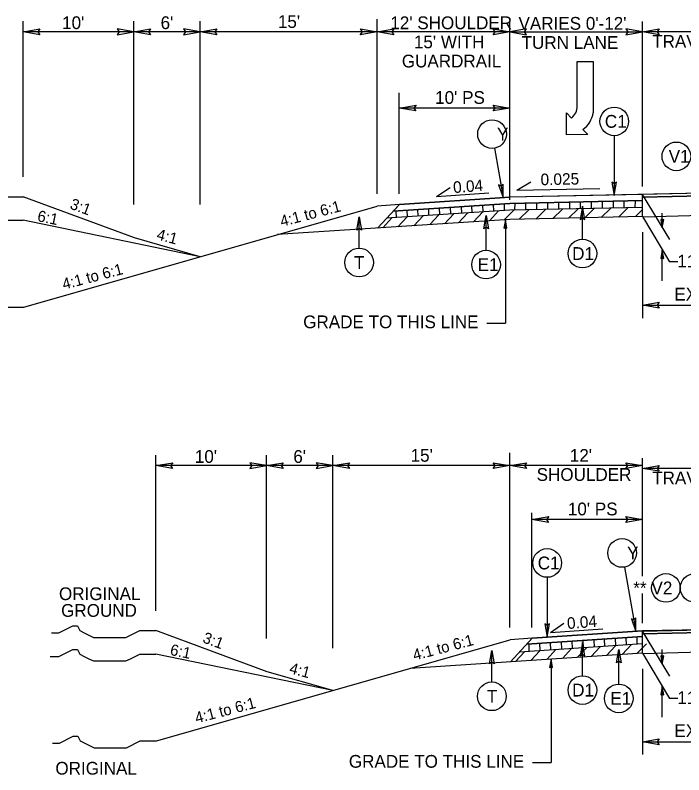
# Model space of a CAD drawing. Extents: x 2176024 to 2177225, y 75947 to 76635.
# Drawn here: x 2176665.1 to 2176725.6, y 76500.8 to 76569.5 of the extents above; entities that cross this region are included whole.
import ezdxf

# ---------------------------------------------------------------- set-up
doc = ezdxf.new("R2010")
doc.units = 0
for name, color, linetype in [('Exist XS Ground Line', 7, 'Continuous'), ('Old_Level_1', 7, 'Continuous'), ('Old_Level_11', 7, 'Continuous'), ('Prop Dimension', 7, 'Continuous'), ('Prop Lane Arrow CELL', 7, 'Continuous'), ('Typical Curb CELL', 7, 'Continuous'), ('Typical Pavement Slope CELL', 7, 'Continuous'), ('Typical Pavement Slope Information CELL', 7, 'Continuous'), ('Typical Shoulder Slope CELL', 7, 'Continuous'), ('Typical Slope Point Local CELL', 7, 'Continuous'), ('Typical Terminator CELL', 7, 'Continuous'), ('Typical Text General CELL', 7, 'Continuous')]:
    doc.layers.add(name, color=color, linetype=linetype)

msp = doc.modelspace()

# ---------------------------------------------------------------- linework, layer by layer
at = {"layer": 'Exist XS Ground Line'}
for p, q in [((2176733.841, 76551.535), (2176721.841, 76551.184)), ((2176733.841, 76512.056), (2176721.841, 76511.705))]:
    msp.add_line(p, q, dxfattribs=at)
at = {"layer": 'Old_Level_1'}
for p, q in [((2176705.492, 76551.53), (2176705.469, 76552.149)), ((2176706.442, 76551.591), (2176706.419, 76552.212)), ((2176707.429, 76551.663), (2176707.406, 76552.276)), ((2176708.384, 76551.72), (2176708.361, 76552.339)), ((2176709.371, 76551.788), (2176709.349, 76552.404)), ((2176710.306, 76551.827), (2176710.312, 76552.446)), ((2176711.294, 76551.855), (2176711.299, 76552.466)), ((2176712.283, 76551.869), (2176712.288, 76552.487)), ((2176713.28, 76551.892), (2176713.285, 76552.508)), ((2176714.269, 76551.911), (2176714.275, 76552.528)), ((2176715.259, 76551.936), (2176715.264, 76552.549)), ((2176716.24, 76551.956), (2176716.245, 76552.57)), ((2176717.219, 76551.977), (2176717.224, 76552.59)), ((2176718.216, 76551.984), (2176718.221, 76552.611)), ((2176719.205, 76552.013), (2176719.21, 76552.631)), ((2176720.179, 76552.025), (2176720.184, 76552.652)), ((2176721.185, 76552.05), (2176721.191, 76552.673)), ((2176699.602, 76551.142), (2176699.58, 76551.763)), ((2176700.589, 76551.215), (2176700.567, 76551.828)), ((2176701.545, 76551.271), (2176701.522, 76551.89)), ((2176702.532, 76551.339), (2176702.509, 76551.955)), ((2176703.519, 76551.4), (2176703.497, 76552.02)), ((2176703.939, 76550.593), (2176704.767, 76551.483)), ((2176704.504, 76551.473), (2176704.482, 76552.084)), ((2176705.196, 76550.681), (2176706.003, 76551.564)), ((2176706.57, 76550.766), (2176707.388, 76551.66)), ((2176708.014, 76550.864), (2176708.833, 76551.76)), ((2176709.34, 76550.954), (2176710.214, 76551.828)), ((2176710.69, 76551.002), (2176711.556, 76551.854)), ((2176712.188, 76551.018), (2176713.071, 76551.885)), ((2176713.725, 76551.068), (2176714.591, 76551.92)), ((2176715.155, 76551.105), (2176716.012, 76551.948)), ((2176716.613, 76551.132), (2176717.477, 76551.982)), ((2176718.111, 76551.147), (2176718.98, 76552.002)), ((2176719.66, 76551.186), (2176720.526, 76552.038)), ((2176721.17, 76551.223), (2176721.838, 76551.881)), ((2176698.357, 76550.232), (2176699.164, 76551.115)), ((2176699.73, 76550.317), (2176700.548, 76551.211)), ((2176701.175, 76550.415), (2176701.994, 76551.311)), ((2176702.617, 76550.512), (2176703.427, 76551.397)), ((2176717.492, 76512.301), (2176717.467, 76512.981)), ((2176718.442, 76512.362), (2176718.417, 76513.044)), ((2176719.429, 76512.435), (2176719.404, 76513.108)), ((2176720.384, 76512.492), (2176720.359, 76513.171)), ((2176721.371, 76512.56), (2176721.346, 76513.236)), ((2176711.602, 76511.913), (2176711.578, 76512.595)), ((2176712.589, 76511.986), (2176712.565, 76512.66)), ((2176713.545, 76512.043), (2176713.52, 76512.722)), ((2176714.532, 76512.111), (2176714.507, 76512.787)), ((2176715.519, 76512.171), (2176715.494, 76512.852)), ((2176716.504, 76512.244), (2176716.48, 76512.916)), ((2176717.196, 76511.452), (2176718.003, 76512.335)), ((2176718.57, 76511.537), (2176719.388, 76512.432)), ((2176720.014, 76511.636), (2176720.833, 76512.531)), ((2176721.34, 76511.725), (2176722.214, 76512.599)), ((2176710.357, 76511.003), (2176711.164, 76511.886)), ((2176711.73, 76511.088), (2176712.548, 76511.983)), ((2176713.175, 76511.187), (2176713.994, 76512.083)), ((2176714.617, 76511.283), (2176715.427, 76512.168)), ((2176715.939, 76511.364), (2176716.767, 76512.254))]:
    msp.add_line(p, q, dxfattribs=at)
at = {"layer": 'Old_Level_11'}
for p, q in [((2176719.287, 76558.556), (2176719.287, 76553.141)), ((2176708.457, 76557.423), (2176709.243, 76552.962)), ((2176716.409, 76549.196), (2176716.409, 76552.192)), ((2176696.216, 76548.384), (2176696.216, 76551.226)), ((2176707.695, 76548.197), (2176707.695, 76551.33)), ((2176720.218, 76519.542), (2176721.243, 76513.723)), ((2176713.218, 76518.621), (2176713.218, 76513.207)), ((2176716.409, 76509.717), (2176716.409, 76512.714)), ((2176708.216, 76509.155), (2176708.216, 76511.997)), ((2176719.695, 76508.968), (2176719.695, 76512.101))]:
    msp.add_line(p, q, dxfattribs=at)
for points in [[(2176708.831, 76554.108), (2176709.243, 76552.962), (2176709.243, 76554.187), (2176709.06, 76553.999)], [(2176719.08, 76554.341), (2176719.287, 76553.141), (2176719.5, 76554.348), (2176719.287, 76554.195)], [(2176716.616, 76550.992), (2176716.409, 76552.192), (2176716.196, 76550.986), (2176716.409, 76551.139)], [(2176696.01, 76550.026), (2176696.216, 76551.226), (2176696.43, 76550.019), (2176696.216, 76550.173)], [(2176707.488, 76550.13), (2176707.695, 76551.33), (2176707.908, 76550.123), (2176707.695, 76550.276)], [(2176713.012, 76514.407), (2176713.218, 76513.207), (2176713.432, 76514.413), (2176713.218, 76514.26)], [(2176720.831, 76514.869), (2176721.243, 76513.723), (2176721.243, 76514.948), (2176721.06, 76514.76)], [(2176716.616, 76511.514), (2176716.409, 76512.714), (2176716.196, 76511.507), (2176716.409, 76511.66)], [(2176708.01, 76510.797), (2176708.216, 76511.997), (2176708.43, 76510.791), (2176708.216, 76510.944)], [(2176719.488, 76510.901), (2176719.695, 76512.101), (2176719.908, 76510.894), (2176719.695, 76511.048)]]:
    msp.add_lwpolyline(points, close=True, dxfattribs=at)
for centre in [(2176719.287, 76559.852), (2176708.233, 76558.699), (2176724.9, 76556.689), (2176716.409, 76547.9), (2176696.216, 76547.088), (2176707.695, 76546.901), (2176719.994, 76520.819), (2176713.218, 76519.917), (2176723.958, 76517.659), (2176726.55, 76517.659), (2176716.409, 76508.421), (2176708.216, 76507.859), (2176719.695, 76507.672)]:
    msp.add_circle(centre, 1.296, dxfattribs=at)
at = {"layer": 'Prop Dimension'}
for p, q in [((2176665.841, 76554.828), (2176665.841, 76568.9)), ((2176675.841, 76552.323), (2176675.841, 76568.9)), ((2176681.841, 76552.323), (2176681.841, 76568.9)), ((2176697.841, 76553.312), (2176697.841, 76569.11)), ((2176709.841, 76552.751), (2176709.841, 76568.874)), ((2176721.841, 76553.949), (2176721.841, 76568.874)), ((2176675.841, 76567.947), (2176665.841, 76567.947)), ((2176681.841, 76567.947), (2176675.841, 76567.947)), ((2176697.841, 76567.947), (2176681.841, 76567.947)), ((2176709.841, 76567.947), (2176697.841, 76567.947)), ((2176709.841, 76567.947), (2176721.841, 76567.947)), ((2176733.841, 76567.947), (2176721.947, 76567.947)), ((2176699.841, 76553.312), (2176699.841, 76562.434)), ((2176709.841, 76561.059), (2176699.841, 76561.059)), ((2176721.796, 76553.238), (2176724.266, 76549.156)), ((2176723.629, 76550.231), (2176723.629, 76551.559)), ((2176709.441, 76550.96), (2176709.441, 76541.605)), ((2176721.841, 76551.237), (2176724.266, 76547.142)), ((2176721.841, 76549.82), (2176721.841, 76542.068)), ((2176723.629, 76545.441), (2176723.629, 76548.217)), ((2176725.046, 76547.142), (2176724.266, 76547.142)), ((2176721.841, 76543.223), (2176745.841, 76543.223)), ((2176707.768, 76541.605), (2176709.441, 76541.605)), ((2176677.841, 76515.6), (2176677.841, 76529.672)), ((2176687.841, 76513.095), (2176687.841, 76529.672)), ((2176693.841, 76512.22), (2176693.841, 76529.672)), ((2176709.841, 76514.083), (2176709.841, 76529.881)), ((2176721.841, 76518.725), (2176721.841, 76529.396)), ((2176687.841, 76528.718), (2176677.841, 76528.718)), ((2176693.841, 76528.718), (2176687.841, 76528.718)), ((2176709.841, 76528.718), (2176693.841, 76528.718)), ((2176721.841, 76528.718), (2176709.841, 76528.718)), ((2176733.841, 76528.468), (2176721.947, 76528.468)), ((2176711.841, 76514.083), (2176711.841, 76524.463)), ((2176721.841, 76523.846), (2176711.841, 76523.846)), ((2176721.841, 76514.47), (2176721.841, 76517.15)), ((2176721.796, 76513.759), (2176724.266, 76509.677)), ((2176721.841, 76511.758), (2176724.266, 76507.663)), ((2176723.629, 76510.752), (2176723.629, 76512.08)), ((2176713.568, 76511.215), (2176713.568, 76501.859)), ((2176721.841, 76510.341), (2176721.841, 76502.59)), ((2176723.629, 76505.963), (2176723.629, 76508.739)), ((2176725.046, 76507.663), (2176724.266, 76507.663)), ((2176721.841, 76503.745), (2176745.841, 76503.745)), ((2176711.895, 76501.859), (2176713.568, 76501.859))]:
    msp.add_line(p, q, dxfattribs=at)
at = {"layer": 'Prop Lane Arrow CELL'}
for p, q in [((2176715.926, 76561.247), (2176715.934, 76565.262)), ((2176715.934, 76565.262), (2176717.382, 76565.26)), ((2176717.382, 76565.26), (2176717.373, 76560.63)), ((2176714.978, 76558.638), (2176714.96, 76560.613)), ((2176714.96, 76560.613), (2176715.42, 76560.151)), ((2176716.449, 76559.118), (2176716.909, 76558.657)), ((2176716.909, 76558.657), (2176714.978, 76558.638))]:
    msp.add_line(p, q, dxfattribs=at)
for centre, radius, start, end in [((2176714.497, 76561.245), 1.437, 310.23549, 359.89367), ((2176715.103, 76560.982), 2.305, 305.9059, 351.2176)]:
    msp.add_arc(centre, radius, start, end, dxfattribs=at)
at = {"layer": 'Typical Curb CELL'}
for p, q in [((2176721.841, 76551.237), (2176721.841, 76553.251)), ((2176721.841, 76511.758), (2176721.841, 76513.772))]:
    msp.add_line(p, q, dxfattribs=at)
at = {"layer": 'Typical Pavement Slope CELL'}
for p, q in [((2176745.841, 76553.751), (2176709.841, 76553.001)), ((2176745.17, 76553.487), (2176721.841, 76553.001)), ((2176699.86, 76552.346), (2176709.841, 76553.001)), ((2176699.86, 76552.346), (2176697.889, 76550.202)), ((2176709.841, 76552.436), (2176699.307, 76551.745)), ((2176721.841, 76552.686), (2176709.841, 76552.436)), ((2176709.841, 76551.819), (2176698.703, 76551.088)), ((2176721.841, 76552.069), (2176709.841, 76551.819)), ((2176681.841, 76547.612), (2176665.841, 76550.907)), ((2176709.841, 76550.987), (2176688.831, 76549.608)), ((2176711.86, 76513.117), (2176721.841, 76513.772)), ((2176745.841, 76514.272), (2176721.841, 76513.772)), ((2176745.17, 76514.008), (2176721.841, 76513.522)), ((2176711.86, 76513.117), (2176709.889, 76510.974)), ((2176721.841, 76513.268), (2176711.367, 76512.581)), ((2176721.841, 76512.59), (2176710.703, 76511.86)), ((2176693.841, 76508.383), (2176677.841, 76511.678)), ((2176721.841, 76511.758), (2176700.831, 76510.379))]:
    msp.add_line(p, q, dxfattribs=at)
at = {"layer": 'Typical Pavement Slope Information CELL'}
for p, q in [((2176710.482, 76553.633), (2176711.743, 76554.395)), ((2176703.213, 76553.061), (2176704.436, 76553.883)), ((2176710.482, 76553.633), (2176717.987, 76553.783)), ((2176703.213, 76553.061), (2176707.959, 76553.387)), ((2176713.508, 76513.637), (2176714.731, 76514.46)), ((2176713.508, 76513.637), (2176718.254, 76513.964))]:
    msp.add_line(p, q, dxfattribs=at)
at = {"layer": 'Typical Shoulder Slope CELL'}
for p, q in [((2176675.894, 76549.31), (2176665.841, 76553.036)), ((2176665.887, 76543.056), (2176697.86, 76552.186)), ((2176699.86, 76552.346), (2176697.86, 76552.186)), ((2176721.841, 76551.237), (2176709.841, 76550.987)), ((2176681.841, 76547.612), (2176675.894, 76549.31)), ((2176687.894, 76510.081), (2176677.841, 76513.807)), ((2176733.841, 76514.022), (2176721.841, 76513.72)), ((2176677.887, 76503.828), (2176709.86, 76512.957)), ((2176711.86, 76513.117), (2176709.86, 76512.957)), ((2176693.841, 76508.383), (2176687.894, 76510.081))]:
    msp.add_line(p, q, dxfattribs=at)
at = {"layer": 'Typical Slope Point Local CELL'}
for p, q in [((2176733.841, 76553.501), (2176721.841, 76553.251)), ((2176721.841, 76553.001), (2176745.17, 76553.487)), ((2176709.841, 76553.001), (2176699.86, 76552.346)), ((2176721.841, 76553.251), (2176709.841, 76553.001)), ((2176721.841, 76552.686), (2176721.841, 76553.251)), ((2176721.841, 76553.251), (2176721.841, 76553.001)), ((2176699.307, 76551.745), (2176709.841, 76552.436)), ((2176699.86, 76552.346), (2176699.307, 76551.745)), ((2176709.841, 76552.436), (2176721.841, 76552.686)), ((2176721.841, 76513.772), (2176711.86, 76513.117)), ((2176733.841, 76514.022), (2176721.841, 76513.772)), ((2176721.841, 76513.522), (2176745.17, 76514.008)), ((2176721.841, 76513.268), (2176721.841, 76513.772)), ((2176721.841, 76513.772), (2176721.841, 76513.522)), ((2176711.367, 76512.581), (2176721.841, 76513.268)), ((2176711.86, 76513.117), (2176711.367, 76512.581))]:
    msp.add_line(p, q, dxfattribs=at)
for points in [[(2176656.406, 76552.828), (2176656.651, 76552.828), (2176657.068, 76552.828), (2176657.486, 76553.036), (2176657.904, 76553.245), (2176658.321, 76553.455), (2176658.739, 76553.455), (2176658.949, 76553.036), (2176659.366, 76552.828), (2176659.784, 76552.618), (2176660.202, 76552.41), (2176660.619, 76552.41), (2176661.037, 76552.41), (2176661.455, 76552.41), (2176661.872, 76552.41), (2176662.29, 76552.41), (2176662.708, 76552.41), (2176663.125, 76552.41), (2176663.543, 76552.618), (2176663.96, 76552.828), (2176664.378, 76553.036), (2176665.005, 76553.036), (2176665.423, 76553.036), (2176665.841, 76553.036)], [(2176656.273, 76550.699), (2176656.651, 76550.699), (2176657.068, 76550.699), (2176657.486, 76550.907), (2176657.904, 76551.116), (2176658.321, 76551.326), (2176658.739, 76551.326), (2176658.949, 76550.907), (2176659.366, 76550.699), (2176659.784, 76550.489), (2176660.202, 76550.281), (2176660.619, 76550.281), (2176661.037, 76550.281), (2176661.455, 76550.281), (2176661.872, 76550.281), (2176662.29, 76550.281), (2176662.708, 76550.281), (2176663.125, 76550.281), (2176663.543, 76550.489), (2176663.96, 76550.699), (2176664.378, 76550.907), (2176665.005, 76550.907), (2176665.423, 76550.907), (2176665.841, 76550.907)], [(2176656.497, 76542.848), (2176656.697, 76542.848), (2176657.115, 76542.848), (2176657.533, 76543.056), (2176657.95, 76543.266), (2176658.368, 76543.476), (2176658.786, 76543.476), (2176658.995, 76543.056), (2176659.413, 76542.848), (2176659.831, 76542.639), (2176660.248, 76542.431), (2176660.666, 76542.431), (2176661.084, 76542.431), (2176661.501, 76542.431), (2176661.919, 76542.431), (2176662.337, 76542.431), (2176662.754, 76542.431), (2176663.172, 76542.431), (2176663.589, 76542.639), (2176664.007, 76542.848), (2176664.425, 76543.056), (2176665.052, 76543.056), (2176665.47, 76543.056), (2176665.887, 76543.056)], [(2176668.406, 76513.599), (2176668.651, 76513.599), (2176669.068, 76513.599), (2176669.486, 76513.807), (2176669.904, 76514.017), (2176670.321, 76514.226), (2176670.739, 76514.226), (2176670.949, 76513.807), (2176671.366, 76513.599), (2176671.784, 76513.389), (2176672.202, 76513.181), (2176672.619, 76513.181), (2176673.037, 76513.181), (2176673.455, 76513.181), (2176673.872, 76513.181), (2176674.29, 76513.181), (2176674.708, 76513.181), (2176675.125, 76513.181), (2176675.543, 76513.389), (2176675.96, 76513.599), (2176676.378, 76513.807), (2176677.005, 76513.807), (2176677.423, 76513.807), (2176677.841, 76513.807)], [(2176668.273, 76511.47), (2176668.651, 76511.47), (2176669.068, 76511.47), (2176669.486, 76511.678), (2176669.904, 76511.888), (2176670.321, 76512.098), (2176670.739, 76512.098), (2176670.949, 76511.678), (2176671.366, 76511.47), (2176671.784, 76511.261), (2176672.202, 76511.053), (2176672.619, 76511.053), (2176673.037, 76511.053), (2176673.455, 76511.053), (2176673.872, 76511.053), (2176674.29, 76511.053), (2176674.708, 76511.053), (2176675.125, 76511.053), (2176675.543, 76511.261), (2176675.96, 76511.47), (2176676.378, 76511.678), (2176677.005, 76511.678), (2176677.423, 76511.678), (2176677.841, 76511.678)], [(2176668.497, 76503.62), (2176668.697, 76503.62), (2176669.115, 76503.62), (2176669.533, 76503.828), (2176669.95, 76504.037), (2176670.368, 76504.247), (2176670.786, 76504.247), (2176670.995, 76503.828), (2176671.413, 76503.62), (2176671.831, 76503.41), (2176672.248, 76503.202), (2176672.666, 76503.202), (2176673.084, 76503.202), (2176673.501, 76503.202), (2176673.919, 76503.202), (2176674.337, 76503.202), (2176674.754, 76503.202), (2176675.172, 76503.202), (2176675.589, 76503.41), (2176676.007, 76503.62), (2176676.425, 76503.828), (2176677.052, 76503.828), (2176677.47, 76503.828), (2176677.887, 76503.828)]]:
    msp.add_lwpolyline(points, dxfattribs=at)
at = {"layer": 'Typical Terminator CELL'}
for points in [[(2176667.35, 76567.687), (2176665.841, 76567.947), (2176667.359, 76568.215), (2176667.166, 76567.947)], [(2176674.331, 76567.687), (2176675.841, 76567.947), (2176674.323, 76568.215), (2176674.516, 76567.947)], [(2176677.35, 76567.687), (2176675.841, 76567.947), (2176677.359, 76568.215), (2176677.166, 76567.947)], [(2176680.331, 76567.687), (2176681.841, 76567.947), (2176680.323, 76568.215), (2176680.516, 76567.947)], [(2176683.35, 76567.687), (2176681.841, 76567.947), (2176683.359, 76568.215), (2176683.166, 76567.947)], [(2176696.331, 76568.207), (2176697.841, 76567.947), (2176696.323, 76567.678), (2176696.516, 76567.947)], [(2176699.35, 76567.687), (2176697.841, 76567.947), (2176699.359, 76568.215), (2176699.166, 76567.947)], [(2176708.331, 76568.207), (2176709.841, 76567.947), (2176708.323, 76567.678), (2176708.516, 76567.947)], [(2176711.35, 76568.207), (2176709.841, 76567.947), (2176711.359, 76567.678), (2176711.166, 76567.947)], [(2176720.331, 76567.687), (2176721.841, 76567.947), (2176720.323, 76568.215), (2176720.516, 76567.947)], [(2176723.35, 76567.687), (2176721.841, 76567.947), (2176723.359, 76568.215), (2176723.166, 76567.947)], [(2176723.35, 76567.687), (2176721.841, 76567.947), (2176723.359, 76568.215), (2176723.166, 76567.947)], [(2176701.35, 76560.799), (2176699.841, 76561.059), (2176701.359, 76561.327), (2176701.166, 76561.059)], [(2176708.331, 76561.319), (2176709.841, 76561.059), (2176708.323, 76560.791), (2176708.516, 76561.059)], [(2176709.571, 76550.206), (2176709.441, 76550.96), (2176709.307, 76550.201), (2176709.441, 76550.298)], [(2176723.497, 76550.985), (2176723.629, 76550.231), (2176723.761, 76550.99), (2176723.627, 76550.893)], [(2176723.761, 76547.463), (2176723.629, 76548.217), (2176723.497, 76547.458), (2176723.631, 76547.555)], [(2176723.35, 76542.963), (2176721.841, 76543.223), (2176723.359, 76543.492), (2176723.166, 76543.223)], [(2176679.35, 76528.458), (2176677.841, 76528.718), (2176679.359, 76528.986), (2176679.166, 76528.718)], [(2176686.331, 76528.458), (2176687.841, 76528.718), (2176686.323, 76528.986), (2176686.516, 76528.718)], [(2176689.35, 76528.458), (2176687.841, 76528.718), (2176689.359, 76528.986), (2176689.166, 76528.718)], [(2176692.331, 76528.458), (2176693.841, 76528.718), (2176692.323, 76528.986), (2176692.516, 76528.718)], [(2176695.35, 76528.458), (2176693.841, 76528.718), (2176695.359, 76528.986), (2176695.166, 76528.718)], [(2176708.331, 76528.978), (2176709.841, 76528.718), (2176708.323, 76528.45), (2176708.516, 76528.718)], [(2176711.35, 76528.458), (2176709.841, 76528.718), (2176711.359, 76528.986), (2176711.166, 76528.718)], [(2176720.331, 76528.978), (2176721.841, 76528.718), (2176720.323, 76528.45), (2176720.516, 76528.718)], [(2176723.35, 76528.208), (2176721.841, 76528.468), (2176723.359, 76528.736), (2176723.166, 76528.468)], [(2176723.35, 76528.208), (2176721.841, 76528.468), (2176723.359, 76528.736), (2176723.166, 76528.468)], [(2176713.35, 76523.586), (2176711.841, 76523.846), (2176713.359, 76524.114), (2176713.166, 76523.846)], [(2176720.331, 76524.106), (2176721.841, 76523.846), (2176720.323, 76523.578), (2176720.516, 76523.846)], [(2176713.698, 76510.46), (2176713.568, 76511.215), (2176713.434, 76510.456), (2176713.568, 76510.553)], [(2176723.497, 76511.507), (2176723.629, 76510.752), (2176723.761, 76511.512), (2176723.627, 76511.415)], [(2176723.761, 76507.984), (2176723.629, 76508.739), (2176723.497, 76507.979), (2176723.631, 76508.076)], [(2176723.35, 76503.485), (2176721.841, 76503.745), (2176723.359, 76504.013), (2176723.166, 76503.745)]]:
    msp.add_lwpolyline(points, close=True, dxfattribs=at)

# ---------------------------------------------------------------- texts
at = {"layer": 'Old_Level_11'}
for s, rotation, p in [('C1', 359.99974, (2176718.431, 76559.272)), ('Y', 359.99974, (2176708.677, 76558.119)), ('V1', 0.00026, (2176724.207, 76556.109)), ('D1', 359.99974, (2176715.475, 76547.32)), ('T', 359.99974, (2176695.759, 76546.508)), ('E1', 359.99974, (2176706.931, 76546.321)), ('Y', 359.99974, (2176720.438, 76520.239)), ('C1', 359.99974, (2176712.362, 76519.337)), ('** V2', 0.00026, (2176721.004, 76517.079)), ('D1', 359.99974, (2176715.475, 76507.841)), ('T', 359.99974, (2176707.759, 76507.279)), ('E1', 359.99974, (2176718.931, 76507.092))]:
    msp.add_text(s, height=1.16, rotation=rotation, dxfattribs=at).set_placement(p)
for p in [(2176724.988, 76546.641), (2176724.988, 76507.163)]:
    msp.add_text('11"', height=1.1533, dxfattribs=at).set_placement(p)
at = {"layer": 'Typical Pavement Slope Information CELL'}
for s, rotation, p in [('0.025', 1.14574, (2176712.631, 76554.076)), ('0.04', 4.26584, (2176704.754, 76553.363)), ('0.04', 4.26584, (2176715.049, 76513.939))]:
    msp.add_text(s, height=1.0429, rotation=rotation, dxfattribs=at).set_placement(p)
at = {"layer": 'Typical Slope Point Local CELL'}
for s, rotation, p in [('3:1', 339.63369, (2176669.988, 76551.988)), ('4:1 to 6:1', 14.73365, (2176689.217, 76550.311)), ('6:1', 348.41207, (2176667.062, 76550.842)), ('4:1', 345.26635, (2176677.837, 76549.19)), ('4:1 to 6:1', 14.73365, (2176669.516, 76544.628)), ('3:1', 339.63369, (2176681.988, 76512.76)), ('4:1 to 6:1', 14.73365, (2176701.217, 76511.083)), ('6:1', 348.41207, (2176679.062, 76511.613)), ('4:1', 345.26635, (2176689.837, 76509.961)), ('4:1 to 6:1', 14.73365, (2176681.516, 76505.399))]:
    msp.add_text(s, height=1.0064, rotation=rotation, dxfattribs=at).set_placement(p)
at = {"layer": 'Typical Text General CELL'}
for s, height, p in [("10'", 1.1533, (2176669.362, 76568.199)), ("6'", 1.1533, (2176678.265, 76568.199)), ("15'", 1.1533, (2176688.871, 76568.301)), ("12' SHOULDER", 1.15334, (2176699.037, 76568.189)), ("VARIES 0'-12'", 1.15334, (2176710.628, 76568.139)), ("15' WITH", 1.1533, (2176701.168, 76566.459)), (' TURN LANE', 1.1533, (2176710.481, 76566.409)), ('TRAVEL LANE', 1.15334, (2176722.715, 76566.505)), ('GUARDRAIL', 1.1533, (2176700.076, 76564.729)), ("10' PS", 1.1533, (2176703.09, 76561.436)), ("EXIST. PAVEMENT 24'", 1.15334, (2176724.722, 76543.651)), ('GRADE TO THIS LINE', 1.15334, (2176691.16, 76541.145)), ("10'", 1.1533, (2176681.362, 76528.97)), ("6'", 1.1533, (2176690.265, 76528.97)), ("15'", 1.1533, (2176700.871, 76529.073)), ("12' ", 1.1533, (2176715.268, 76529.068)), ('SHOULDER', 1.1533, (2176712.267, 76527.338)), ('TRAVEL LANE', 1.15334, (2176722.715, 76527.027)), ("10' PS", 1.1533, (2176715.09, 76524.223)), ('ORIGINAL', 1.1533, (2176669.075, 76516.559)), ('GROUND', 1.1533, (2176669.269, 76515.047)), ("EXIST. PAVEMENT 24'", 1.15334, (2176724.722, 76504.172)), ('GRADE TO THIS LINE', 1.15334, (2176695.287, 76501.399)), ('ORIGINAL', 1.1533, (2176668.752, 76500.776))]:
    msp.add_text(s, height=height, dxfattribs=at).set_placement(p)

doc.saveas('drawing.dxf')
